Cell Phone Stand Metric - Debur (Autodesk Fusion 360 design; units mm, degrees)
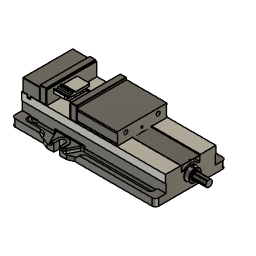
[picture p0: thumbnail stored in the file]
description: HaasClamp
derived_base_feature "Derived Base Feature" bodies "Stand Body"
align "Align1"
base_feature "Base Feature1"
base_feature "Base Feature1"
base_feature "Base Feature1"
base_feature "Base Feature1"
base_feature "Base Feature1"
base_feature "Base Feature1"
base_feature "Base Feature1"
base_feature "Base Feature1"
base_feature "Base Feature1"
base_feature "Base Feature1"
as_built_joint "As-built1"
as_built_joint "As-built2"
as_built_joint "As-built3"
joint_origin "JointOrigin1" OffsetX 0 OffsetY 0 OffsetZ 0 AngleZ 0
joint "Assemble1" alignAngle 180 alignOffsetX 0 alignOffsetY 0 alignOffsetZ 0 (= "jaw_width_haas_050002") SlideMaximum 22.5 SlideMinimum 0
position "Position1"
sketch "Sketch1" plane through (0, -72.5, 0) normal (0, -1, 0) x axis (1, 0, 0)
  line L1 (75, 73) -> (-75, 73)
  line L2 (76, 74) -> (75, 73)
  line L3 (76, 116.5) -> (76, 74)
  line L4 (75, 117.5) -> (76, 116.5)
  line L5 (-75, 117.5) -> (75, 117.5)
  line L6 (-76, 116.5) -> (-75, 117.5)
  line L7 (-76, 74) -> (-76, 116.5)
  line L8 (-75, 73) -> (-76, 74)
  line L9 (76.4, 114.275) -> (-76, 114.275)
  line L10 (76.4, 73) -> (76.4, 114.275)
  line L11 (-76, 73) -> (76.4, 73)
  line L12 (-76, 114.275) -> (-76, 73)
  circle C1 centre (49.21, 96.8) radius 11
  circle C2 centre (-49.21, 96.8) radius 11
  point P14 (76.4, 73)
  point P12 (-76, 114.275)
  point P13 (76.4, 114.275)
  horizontal L9
  vertical L10
  horizontal L11
  vertical L12
  coincident L1 P14
  coincident L7 P12
  dimension "d16" distance P12 P13 = 152.4
  dimension "d17" distance P13 P14 = 41.275
place_component sketch "Sketch1"
extrude "Extrude1" new body sketch "Sketch1" profile of L1 L2 L3 L7 L8 C1 C2 L9 L11 L12 along normal blind 3.175
place_component sketch "Sketch1"
extrude "Extrude1" sketch "Sketch1" profile of L1 L2 L3 L7 L8 C1 C2 L9 L11 L12 blind -3.175
as_built_joint "As-built5"
as_built_joint "As-built6"
sketch "Sketch1" plane through (0, 0, 0) normal (0, 0, -1) x axis (1, 0, 0)
  line L1 (16.5, -37.5) -> (-16.5, -37.5)
  line L2 (20, 34) -> (20, -34)
  line L3 (-16.5, 37.5) -> (16.5, 37.5)
  line L4 (-20, -34) -> (-20, 34)
  line L5 (-38.1, -40) -> (38.1, -40)
  line L6 (-38.1, 40) -> (-38.1, -40)
  line L7 (38.1, 40) -> (-38.1, 40)
  line L8 (38.1, -40) -> (38.1, 40)
  line L9 (-38.1, 40) -> (38.1, -40)
  line L10 (38.1, 40) -> (-38.1, -40)
  arc A1 centre (-16.5, -34) radius 3.5 clockwise from (-16.5, -37.5) to (-20, -34)
  arc A2 centre (16.5, -34) radius 3.5 clockwise from (20, -34) to (16.5, -37.5)
  arc A3 centre (16.5, 34) radius 3.5 clockwise from (16.5, 37.5) to (20, 34)
  arc A4 centre (-16.5, 34) radius 3.5 clockwise from (-20, 34) to (-16.5, 37.5)
  point P18 (0, 0)
  point P1 (0, 0)
  point P16 (-38.1, 40)
  point P17 (38.1, 40)
  point P15 (-38.1, -40)
  horizontal L5
  perpendicular L5 L6
  parallel L5 L7
  parallel L6 L8
  coincident L9 P18
  coincident L10 P18
  coincident P1 P18
  dimension "d1" distance P16 P17 = 76.2
  dimension "d2" distance P15 P16 = 80
extrude "Extrude1" new body sketch "Sketch1" profile of A1 L1 A2 L2 A3 L3 A4 L4 L5 L6 L7 L8 against normal blind 10 bodies "Stock"
position "Position1"
ground "Pin"
position "Position2"
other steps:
create_component "CreateComponent1"
create_component "CreateComponent2"
create_component "CreateComponent3"
create_component "CreateComponent4"
create_component "CreateComponent5"
create_component "CreateComponent6"
create_component "CreateComponent7"
create_component "CreateComponent8"
create_component "CreateComponent9"
create_component "CreateComponent10"
joint_origin "JointOrigin10"
joint_origin "JointOrigin11"
create_component "CreateComponent11" sketch "Sketch1"
create_component "CreateComponent12" sketch "Sketch1"
create_component "CreateComponent1"
named bodies: "Stand Body", "Stock"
